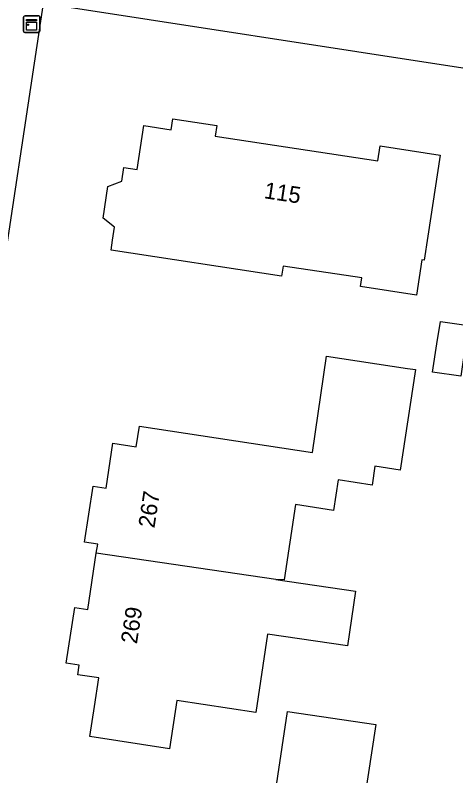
# Model space of a CAD drawing. Extents: x 161486 to 162249, y 379484 to 380829.
# Drawn here: x 161674.13 to 161700.97, y 380529.72 to 380576.04 of the extents above; entities that cross this region are included whole.
import ezdxf

# ---------------------------------------------------------------- set-up
doc = ezdxf.new("R2010")
doc.units = 0
for name, color, linetype in [('IMGEO_Kast', 7, 'Continuous'), ('IMGEO_Pand', 7, 'Continuous'), ('IMGEO_Pand_nummerreeks', 7, 'Continuous'), ('IMGEO_Voetpad_open', 7, 'Continuous')]:
    doc.layers.add(name, color=color, linetype=linetype)

msp = doc.modelspace()

# ---------------------------------------------------------------- linework, layer by layer
at = {"layer": 'IMGEO_Kast'}
for p, q in [((161674.705, 380576), (161675.546, 380576)), ((161675.546, 380576), (161674.705, 380576)), ((161674.63, 380575.075), (161674.63, 380575.916)), ((161674.63, 380575.916), (161674.63, 380575.075)), ((161675.63, 380575.925), (161675.63, 380575.084)), ((161675.63, 380575.084), (161675.63, 380575.925)), ((161675.555, 380575), (161674.714, 380575)), ((161674.714, 380575), (161675.555, 380575))]:
    msp.add_line(p, q, dxfattribs=at)
for points in [[(161674.825, 380575.79), (161675.425, 380575.79), (161675.425, 380575.705), (161674.825, 380575.705), (161674.825, 380575.79)], [(161674.825, 380575.615), (161675.425, 380575.615), (161675.425, 380575.126), (161674.825, 380575.126), (161674.825, 380575.615)]]:
    msp.add_lwpolyline(points, dxfattribs=at)
msp.add_circle((161674.909, 380575.464), 0.0377, dxfattribs=at)
for centre, start, end in [((161674.708, 380575.922), 92.4484, 184.2845), ((161674.708, 380575.922), 92.4484, 184.2845), ((161675.552, 380575.922), 2.4484, 94.2845), ((161675.552, 380575.922), 2.4484, 94.2845), ((161674.708, 380575.078), 182.4484, 274.2845), ((161674.708, 380575.078), 182.4484, 274.2845), ((161675.552, 380575.078), 272.4484, 4.2845), ((161675.552, 380575.078), 272.4484, 4.2845)]:
    msp.add_arc(centre, 0.0779, start, end, dxfattribs=at)
at = {"layer": 'IMGEO_Pand'}
for points in [[(161698.578, 380558.998), (161695.158, 380559.518), (161695.237, 380560.041), (161690.449, 380560.77), (161690.356, 380560.156), (161679.969, 380561.736), (161680.062, 380562.351), (161680.18, 380563.132), (161679.484, 380563.689), (161679.777, 380565.615), (161680.622, 380565.945), (161680.748, 380566.777), (161681.552, 380566.655), (161681.958, 380569.324), (161683.626, 380569.07), (161683.727, 380569.738), (161686.418, 380569.329), (161686.319, 380568.677), (161696.227, 380567.169), (161696.366, 380568.08), (161700.019, 380567.524), (161699.266, 380562.582), (161699.045, 380561.129), (161698.905, 380561.15), (161698.578, 380558.998)], [(161699.56, 380554.312), (161699.822, 380556.036), (161700.029, 380557.396), (161701.739, 380557.15), (161701.53, 380555.776), (161701.268, 380554.052), (161699.56, 380554.312)], [(161679.07, 380543.282), (161679.153, 380543.827), (161678.351, 380543.949), (161678.87, 380547.358), (161679.666, 380547.237), (161680.084, 380549.978), (161681.499, 380549.762), (161681.691, 380551.023), (161692.238, 380549.418), (161693.093, 380555.286), (161698.037, 380554.534), (161698.515, 380554.461), (161697.583, 380548.337), (161696.047, 380548.57), (161695.873, 380547.424), (161693.799, 380547.739), (161693.517, 380545.883), (161691.202, 380546.236), (161690.507, 380541.666), (161690.01, 380541.673)], [(161690.01, 380541.673), (161694.865, 380540.959), (161694.376, 380537.629), (161689.504, 380538.346), (161688.779, 380533.586), (161683.968, 380534.318), (161683.52, 380531.373), (161678.676, 380532.11), (161678.955, 380533.943), (161679.219, 380535.679), (161677.944, 380535.873), (161678.034, 380536.469), (161677.237, 380536.591), (161677.752, 380539.976), (161678.549, 380539.854), (161679.07, 380543.282)], [(161690.01, 380541.673), (161679.07, 380543.282)], [(161689.804, 380527.537), (161690.723, 380533.648), (161696.091, 380532.843), (161695.174, 380526.728)]]:
    msp.add_lwpolyline(points, dxfattribs=at)
at = {"layer": 'IMGEO_Voetpad_open'}
for points in [[(161675.834, 380576.755), (161672.785, 380556.708)], [(161746.578, 380565.893), (161701.408, 380572.822), (161675.834, 380576.755)]]:
    msp.add_lwpolyline(points, dxfattribs=at)

# ---------------------------------------------------------------- texts
at = {"layer": 'IMGEO_Pand_nummerreeks'}
for s, rotation, p in [('115', 351.3999, (161689.246, 380564.904)), ('267', 81.3293, (161682.608, 380544.773)), ('269', 81.36, (161681.542, 380537.722))]:
    msp.add_text(s, height=1, rotation=rotation, dxfattribs=at).set_placement(p)

doc.saveas('drawing.dxf')
